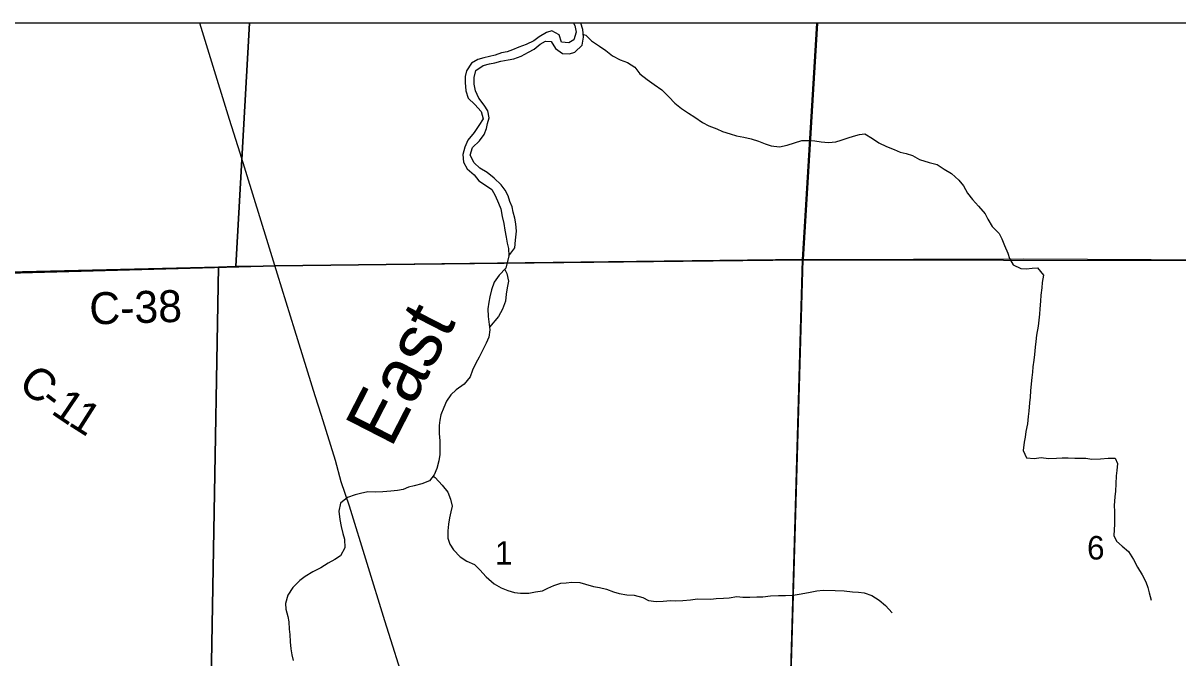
# Model space of a CAD drawing. Extents: x 1772825 to 1773716, y 1138558 to 1139032.
# Drawn here: x 1772827.336 to 1772828.362, y 1138563.795 to 1138564.359 of the extents above; entities that cross this region are included whole.
import ezdxf

# ---------------------------------------------------------------- set-up
doc = ezdxf.new("R2010")
doc.units = 0
for name, color, linetype in [('GM_X_County_Road_Text', 7, 'Continuous'), ('GM_X_Minor_River', 7, 'Continuous'), ('GM_X_Minor_River_Text', 7, 'Continuous'), ('GM_X_Rail_Line', 7, 'Continuous'), ('GM_X_Section', 7, 'Continuous'), ('GM_X_Section_Text', 7, 'Continuous'), ('GM_X_Township', 7, 'Continuous')]:
    doc.layers.add(name, color=color, linetype=linetype)

msp = doc.modelspace()

# ---------------------------------------------------------------- linework, layer by layer
at = {"layer": 'GM_X_Minor_River'}
for points in [[(1772827.8253, 1138564.3594), (1772827.8263, 1138564.3572), (1772827.8276, 1138564.3515), (1772827.8256, 1138564.3446), (1772827.8209, 1138564.3418), (1772827.8146, 1138564.3426), (1772827.8124, 1138564.3489), (1772827.806, 1138564.3527), (1772827.8012, 1138564.351), (1772827.7948, 1138564.3473), (1772827.79, 1138564.3437), (1772827.7832, 1138564.3403), (1772827.7767, 1138564.3379), (1772827.771, 1138564.3357), (1772827.7661, 1138564.334), (1772827.7613, 1138564.3329), (1772827.7556, 1138564.331), (1772827.7505, 1138564.3297), (1772827.7454, 1138564.3286), (1772827.7403, 1138564.3271), (1772827.7344, 1138564.3237), (1772827.7302, 1138564.3171), (1772827.729, 1138564.312), (1772827.7288, 1138564.3065), (1772827.7295, 1138564.2993), (1772827.7317, 1138564.2928), (1772827.7376, 1138564.2871), (1772827.743, 1138564.2808), (1772827.7449, 1138564.2743), (1772827.741, 1138564.2684), (1772827.7368, 1138564.2622), (1772827.7313, 1138564.2554), (1772827.7286, 1138564.249), (1772827.7267, 1138564.2425), (1772827.7274, 1138564.2359), (1772827.7308, 1138564.2298), (1772827.7368, 1138564.2244), (1772827.7411, 1138564.2191), (1772827.7462, 1138564.216), (1772827.7526, 1138564.2116), (1772827.7556, 1138564.2061), (1772827.7584, 1138564.1994), (1772827.7605, 1138564.1943), (1772827.7619, 1138564.1876), (1772827.7632, 1138564.1812), (1772827.7641, 1138564.1753), (1772827.7654, 1138564.1692), (1772827.7661, 1138564.1637), (1772827.7673, 1138564.159), (1772827.7676, 1138564.1525)], [(1772827.7676, 1138564.1525), (1772827.7731, 1138564.1597), (1772827.7736, 1138564.1663), (1772827.7744, 1138564.1743), (1772827.774, 1138564.1811), (1772827.7731, 1138564.1859), (1772827.7716, 1138564.1912), (1772827.7707, 1138564.1961), (1772827.7687, 1138564.2009), (1772827.767, 1138564.206), (1772827.7646, 1138564.211), (1772827.7608, 1138564.2157), (1772827.7548, 1138564.2217), (1772827.7484, 1138564.2266), (1772827.7419, 1138564.2305), (1772827.737, 1138564.2351), (1772827.7333, 1138564.2421), (1772827.7354, 1138564.2487), (1772827.7415, 1138564.2548), (1772827.7457, 1138564.2603), (1772827.7478, 1138564.2656), (1772827.7488, 1138564.2703), (1772827.7502, 1138564.2752), (1772827.7489, 1138564.2815), (1772827.7459, 1138564.2866), (1772827.741, 1138564.2927), (1772827.738, 1138564.2992), (1772827.7369, 1138564.3051), (1772827.737, 1138564.311), (1772827.7383, 1138564.3172), (1772827.7448, 1138564.3218), (1772827.7505, 1138564.3232), (1772827.7552, 1138564.3242), (1772827.7605, 1138564.3255), (1772827.767, 1138564.3268), (1772827.7723, 1138564.3277), (1772827.7787, 1138564.3299), (1772827.7852, 1138564.3337), (1772827.7901, 1138564.3363), (1772827.7955, 1138564.3408), (1772827.8004, 1138564.3434), (1772827.8053, 1138564.343), (1772827.8091, 1138564.3368), (1772827.8153, 1138564.3325), (1772827.8216, 1138564.3321), (1772827.8265, 1138564.3336), (1772827.8328, 1138564.3398), (1772827.8342, 1138564.3469), (1772827.8336, 1138564.3537), (1772827.8317, 1138564.3594)], [(1772827.834, 1138564.3494), (1772827.8363, 1138564.3487), (1772827.8413, 1138564.3436), (1772827.8483, 1138564.339), (1772827.854, 1138564.3352), (1772827.86, 1138564.3302), (1772827.8666, 1138564.3269), (1772827.8732, 1138564.3244), (1772827.8796, 1138564.3204), (1772827.8843, 1138564.3143), (1772827.8907, 1138564.3093), (1772827.8968, 1138564.3049), (1772827.9036, 1138564.3001), (1772827.91, 1138564.2938), (1772827.9152, 1138564.2883), (1772827.9211, 1138564.2835), (1772827.9275, 1138564.2795), (1772827.933, 1138564.2758), (1772827.9399, 1138564.2711), (1772827.9456, 1138564.268), (1772827.9526, 1138564.2653), (1772827.9575, 1138564.2632), (1772827.9645, 1138564.261), (1772827.97, 1138564.2593), (1772827.9766, 1138564.2581), (1772827.9832, 1138564.2564), (1772827.9895, 1138564.2544), (1772827.9957, 1138564.2521), (1772828.0008, 1138564.2502), (1772828.0082, 1138564.2494), (1772828.015, 1138564.2509), (1772828.0215, 1138564.2531), (1772828.0281, 1138564.255), (1772828.0345, 1138564.2551), (1772828.0396, 1138564.2549), (1772828.0453, 1138564.2539), (1772828.052, 1138564.2533), (1772828.0584, 1138564.254), (1772828.0631, 1138564.2553), (1772828.0694, 1138564.2574), (1772828.0741, 1138564.2589), (1772828.0793, 1138564.2605), (1772828.0842, 1138564.2611), (1772828.091, 1138564.2569), (1772828.0965, 1138564.2529), (1772828.1034, 1138564.2496), (1772828.1102, 1138564.2471), (1772828.1155, 1138564.2448), (1772828.1208, 1138564.2434), (1772828.1265, 1138564.2417), (1772828.1329, 1138564.2382), (1772828.1414, 1138564.2355), (1772828.1484, 1138564.2336), (1772828.1548, 1138564.2297), (1772828.1611, 1138564.2257), (1772828.1678, 1138564.2198), (1772828.1718, 1138564.2148), (1772828.1755, 1138564.2083), (1772828.18, 1138564.2026), (1772828.1853, 1138564.1967), (1772828.1911, 1138564.1898), (1772828.1936, 1138564.1851), (1772828.1973, 1138564.1786), (1772828.2035, 1138564.1725), (1772828.206, 1138564.1677), (1772828.2084, 1138564.1616), (1772828.2112, 1138564.155), (1772828.2129, 1138564.15), (1772828.216, 1138564.1445), (1772828.2227, 1138564.1411), (1772828.2278, 1138564.1408), (1772828.2329, 1138564.1414), (1772828.2376, 1138564.1417), (1772828.2429, 1138564.1354), (1772828.2417, 1138564.1288), (1772828.2415, 1138564.124), (1772828.2407, 1138564.1174), (1772828.2403, 1138564.1121), (1772828.2397, 1138564.1055), (1772828.2393, 1138564.1007), (1772828.2387, 1138564.0952), (1772828.2381, 1138564.0901), (1772828.2367, 1138564.0821), (1772828.2361, 1138564.0764), (1772828.2355, 1138564.0713), (1772828.2349, 1138564.0647), (1772828.2343, 1138564.0597), (1772828.2335, 1138564.0539), (1772828.2333, 1138564.0491), (1772828.2327, 1138564.0444), (1772828.2319, 1138564.0387), (1772828.2314, 1138564.0326), (1772828.231, 1138564.0269), (1772828.2306, 1138564.0218), (1772828.2298, 1138564.0144), (1772828.2294, 1138564.0097), (1772828.2288, 1138564.003), (1772828.2272, 1138563.9962), (1772828.2266, 1138563.9914), (1772828.2259, 1138563.9867), (1772828.2249, 1138563.9793)], [(1772827.7676, 1138564.1525), (1772827.7651, 1138564.1415), (1772827.7592, 1138564.1353), (1772827.7548, 1138564.129), (1772827.7524, 1138564.1224), (1772827.7509, 1138564.1162), (1772827.7499, 1138564.1112), (1772827.7491, 1138564.1055), (1772827.7493, 1138564.0985), (1772827.75, 1138564.0938), (1772827.7509, 1138564.0867), (1772827.7499, 1138564.0801), (1772827.7476, 1138564.0748), (1772827.744, 1138564.0678), (1772827.7413, 1138564.0623), (1772827.7384, 1138564.057), (1772827.7355, 1138564.0509), (1772827.7334, 1138564.0449), (1772827.7279, 1138564.0385), (1772827.721, 1138564.0334), (1772827.7163, 1138564.029), (1772827.7124, 1138564.0232), (1772827.7099, 1138564.0177), (1772827.7072, 1138564.0112), (1772827.7063, 1138564.0063), (1772827.7059, 1138564.0016), (1772827.7058, 1138563.9944), (1772827.7063, 1138563.9881), (1772827.7063, 1138563.9759), (1772827.7055, 1138563.9701), (1772827.7037, 1138563.9634), (1772827.7012, 1138563.9578), (1772827.6972, 1138563.9525), (1772827.6904, 1138563.9497), (1772827.6837, 1138563.948), (1772827.6784, 1138563.9469), (1772827.6737, 1138563.9448), (1772827.6688, 1138563.9439), (1772827.6627, 1138563.9432), (1772827.6557, 1138563.9428), (1772827.649, 1138563.9423), (1772827.6424, 1138563.9427), (1772827.636, 1138563.9411), (1772827.631, 1138563.9399), (1772827.6242, 1138563.9377), (1772827.6181, 1138563.9326), (1772827.6166, 1138563.9256), (1772827.6176, 1138563.918), (1772827.6187, 1138563.9119), (1772827.6202, 1138563.9055), (1772827.6215, 1138563.9005), (1772827.622, 1138563.8929), (1772827.6182, 1138563.8857), (1772827.6131, 1138563.8825), (1772827.6072, 1138563.8792), (1772827.6007, 1138563.875), (1772827.5935, 1138563.8715), (1772827.5866, 1138563.8675), (1772827.5819, 1138563.8639), (1772827.5756, 1138563.8577), (1772827.5712, 1138563.8509), (1772827.5693, 1138563.8435), (1772827.5694, 1138563.8384), (1772827.5713, 1138563.8317), (1772827.5722, 1138563.827), (1772827.5725, 1138563.8207), (1772827.5731, 1138563.8158), (1772827.5734, 1138563.8093), (1772827.5739, 1138563.803), (1772827.5748, 1138563.7977), (1772827.5759, 1138563.7926)], [(1772827.7641, 1138564.1405), (1772827.766, 1138564.1368), (1772827.7673, 1138564.1301), (1772827.7663, 1138564.1242), (1772827.7653, 1138564.1185), (1772827.7647, 1138564.1121), (1772827.762, 1138564.1051), (1772827.7584, 1138564.0986), (1772827.7506, 1138564.089)], [(1772828.2249, 1138563.9793), (1772828.228, 1138563.973), (1772828.2347, 1138563.9724), (1772828.2409, 1138563.9731), (1772828.2474, 1138563.9723), (1772828.2546, 1138563.9727), (1772828.2595, 1138563.9728), (1772828.2648, 1138563.9728), (1772828.2707, 1138563.9726), (1772828.2756, 1138563.9727), (1772828.2807, 1138563.9725), (1772828.286, 1138563.9717), (1772828.2936, 1138563.9719), (1772828.3006, 1138563.9726), (1772828.3068, 1138563.9726), (1772828.3087, 1138563.9678), (1772828.3083, 1138563.9617), (1772828.3077, 1138563.9568), (1772828.3073, 1138563.9498), (1772828.307, 1138563.9433), (1772828.3064, 1138563.9382), (1772828.3058, 1138563.9306), (1772828.306, 1138563.9251), (1772828.3061, 1138563.9204), (1772828.3061, 1138563.9139), (1772828.3059, 1138563.909), (1772828.3056, 1138563.9038), (1772828.3079, 1138563.8989), (1772828.3128, 1138563.8945), (1772828.3184, 1138563.8895), (1772828.3231, 1138563.8825), (1772828.3265, 1138563.8758), (1772828.3308, 1138563.869), (1772828.3338, 1138563.8627), (1772828.3357, 1138563.8577), (1772828.337, 1138563.8528), (1772828.3388, 1138563.8463)], [(1772827.7004, 1138563.9566), (1772827.7022, 1138563.9553), (1772827.7086, 1138563.9486), (1772827.7134, 1138563.9425), (1772827.7159, 1138563.9362), (1772827.7173, 1138563.9299), (1772827.7162, 1138563.9248), (1772827.715, 1138563.9195), (1772827.7142, 1138563.914), (1772827.7134, 1138563.9079), (1772827.7134, 1138563.9015), (1772827.7154, 1138563.8962), (1772827.7186, 1138563.891), (1772827.7244, 1138563.8849), (1772827.7303, 1138563.8811), (1772827.7371, 1138563.8782), (1772827.7418, 1138563.8734), (1772827.7476, 1138563.8671), (1772827.7546, 1138563.8608), (1772827.7608, 1138563.8572), (1772827.7669, 1138563.8549), (1772827.7727, 1138563.8533), (1772827.7782, 1138563.8527), (1772827.7854, 1138563.8527), (1772827.7915, 1138563.8538), (1772827.7977, 1138563.8547), (1772827.8025, 1138563.8571), (1772827.8076, 1138563.8594), (1772827.8139, 1138563.8614), (1772827.8188, 1138563.8619), (1772827.8237, 1138563.8625), (1772827.8309, 1138563.8621), (1772827.836, 1138563.8607), (1772827.843, 1138563.8586), (1772827.8483, 1138563.8576), (1772827.8546, 1138563.856), (1772827.8608, 1138563.8537), (1772827.8659, 1138563.8524), (1772827.8727, 1138563.851), (1772827.8792, 1138563.8508), (1772827.8867, 1138563.8486), (1772827.892, 1138563.8461), (1772827.8986, 1138563.8451), (1772827.9049, 1138563.8455), (1772827.9113, 1138563.846), (1772827.9163, 1138563.8458), (1772827.9223, 1138563.846), (1772827.9291, 1138563.8467), (1772827.9354, 1138563.8474), (1772827.9473, 1138563.8473), (1772827.9521, 1138563.8477), (1772827.9585, 1138563.8482), (1772827.9636, 1138563.8484), (1772827.9703, 1138563.8495), (1772827.9756, 1138563.8489), (1772827.9818, 1138563.849), (1772827.9882, 1138563.8492), (1772827.9934, 1138563.8493), (1772828.0004, 1138563.8502), (1772828.0074, 1138563.8506), (1772828.0136, 1138563.8505), (1772828.0206, 1138563.8509), (1772828.0258, 1138563.8516), (1772828.0341, 1138563.8531), (1772828.0415, 1138563.8545), (1772828.0472, 1138563.8551), (1772828.0578, 1138563.855), (1772828.0659, 1138563.8546), (1772828.0733, 1138563.8538), (1772828.0786, 1138563.8534), (1772828.0837, 1138563.853), (1772828.0903, 1138563.8505), (1772828.0969, 1138563.8462), (1772828.1026, 1138563.8415), (1772828.1086, 1138563.835)]]:
    msp.add_lwpolyline(points, dxfattribs=at)
at = {"layer": 'GM_X_Rail_Line'}
msp.add_lwpolyline([(1772827.8706, 1138563.1413), (1772827.8407, 1138563.2374), (1772827.7921, 1138563.3941), (1772827.7153, 1138563.6421), (1772827.6861, 1138563.736), (1772827.6766, 1138563.7668), (1772827.6576, 1138563.828), (1772827.6261, 1138563.9298), (1772827.6187, 1138563.9517), (1772827.6135, 1138563.9705), (1772827.6011, 1138564.0104), (1772827.5956, 1138564.028), (1772827.5776, 1138564.0864), (1772827.5622, 1138564.1363), (1772827.5526, 1138564.1669), (1772827.5289, 1138564.2438), (1772827.5195, 1138564.2738), (1772827.5026, 1138564.3286), (1772827.4929, 1138564.3594), (1772827.4929, 1138564.3594)], dxfattribs=at)
at = {"layer": 'GM_X_Section'}
for p, q in [((1772827.5371, 1138564.3594), (1772827.0362, 1138564.3594)), ((1772828.0416, 1138564.3594), (1772827.5371, 1138564.3594)), ((1772828.5624, 1138564.3594), (1772828.0416, 1138564.3594))]:
    msp.add_line(p, q, dxfattribs=at)
for points in [[(1772827.0362, 1138564.3594), (1772827.0242, 1138564.1311), (1772827.5097, 1138564.1426), (1772827.5249, 1138564.1432), (1772827.5371, 1138564.3594)], [(1772827.5371, 1138564.3594), (1772827.5249, 1138564.1432), (1772828.0289, 1138564.1489), (1772828.0416, 1138564.3594)], [(1772828.0416, 1138564.3594), (1772828.0289, 1138564.1489), (1772828.5651, 1138564.1482), (1772828.5624, 1138564.3594)]]:
    msp.add_lwpolyline(points, dxfattribs=at)
for points in [[(1772827.5097, 1138564.1426), (1772827.5006, 1138563.6402), (1772826.9989, 1138563.6423), (1772826.9986, 1138564.1307), (1772827.0242, 1138564.1311)], [(1772828.0289, 1138564.1489), (1772828.0145, 1138563.6476), (1772827.5006, 1138563.6402), (1772827.5097, 1138564.1426), (1772827.5249, 1138564.1432)], [(1772828.5651, 1138564.1482), (1772828.55, 1138563.6502), (1772828.0145, 1138563.6476), (1772828.0289, 1138564.1489)]]:
    msp.add_lwpolyline(points, close=True, dxfattribs=at)
at = {"layer": 'GM_X_Township'}
msp.add_line((1772831.0226, 1138564.3594), (1772828.0421, 1138564.3594), dxfattribs=at)
for points in [[(1772828.0421, 1138564.3594), (1772825.3579, 1138564.3594), (1772825.3579, 1138564.139)], [(1772825.3579, 1138564.139), (1772825.5143, 1138564.1347), (1772825.7637, 1138564.1277), (1772826.0128, 1138564.1249), (1772826.2589, 1138564.1226), (1772826.2673, 1138564.1226), (1772826.5057, 1138564.1217), (1772826.5183, 1138564.1215), (1772827.0006, 1138564.1306), (1772827.0257, 1138564.131), (1772827.2901, 1138564.1363), (1772827.5601, 1138564.1437), (1772828.0292, 1138564.1491), (1772828.0421, 1138564.3594)], [(1772828.0421, 1138564.3594), (1772828.0292, 1138564.1491), (1772828.2255, 1138564.1497), (1772828.5649, 1138564.148), (1772828.7229, 1138564.1462), (1772829.0062, 1138564.1402), (1772829.258, 1138564.138), (1772829.3013, 1138564.1384), (1772829.5426, 1138564.1379), (1772829.6188, 1138564.1396), (1772829.7041, 1138564.1368), (1772829.7207, 1138564.137), (1772829.8486, 1138564.1368), (1772830.2648, 1138564.1416), (1772830.3453, 1138564.145), (1772830.4944, 1138564.15), (1772831.0202, 1138564.1762), (1772831.0226, 1138564.3594)], [(1772828.0013, 1138563.146), (1772828.0147, 1138563.6455), (1772828.0292, 1138564.1491), (1772827.5601, 1138564.1437), (1772827.2901, 1138564.1363), (1772827.0257, 1138564.131), (1772827.0006, 1138564.1306), (1772826.5183, 1138564.1215)], [(1772828.0013, 1138563.146), (1772828.0147, 1138563.6455), (1772828.0292, 1138564.1491), (1772828.2255, 1138564.1497), (1772828.5649, 1138564.148), (1772828.7229, 1138564.1462), (1772829.0062, 1138564.1402), (1772829.258, 1138564.138)]]:
    msp.add_lwpolyline(points, dxfattribs=at)

# ---------------------------------------------------------------- texts
at = {"layer": 'GM_X_County_Road_Text'}
for s, height, rotation, p in [('C-38', 0.02841, 1.7153, (1772827.3952, 1138564.0914)), ('C', 0.0284, 320.9525, (1772827.3303, 1138564.0362)), ('-', 0.0284, 322.9348, (1772827.3492, 1138564.0208)), ('1', 0.0284, 325.8734, (1772827.3598, 1138564.0129)), ('1', 0.0284, 327.5634, (1772827.3751, 1138564.0026))]:
    msp.add_text(s, height=height, rotation=rotation, dxfattribs=at).set_placement(p)
at = {"layer": 'GM_X_Minor_River_Text'}
msp.add_text('East', height=0.04737, rotation=62.8587, dxfattribs=at).set_placement((1772827.663, 1138563.9807))
at = {"layer": 'GM_X_Section_Text'}
for s, p in [('1', (1772827.7554, 1138563.8779)), ('6', (1772828.2817, 1138563.8825))]:
    msp.add_text(s, height=0.0209, rotation=0, dxfattribs=at).set_placement(p)

doc.saveas('drawing.dxf')
